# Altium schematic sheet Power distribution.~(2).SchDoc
size A3; SheetNumber: 4; SheetTotal: 4
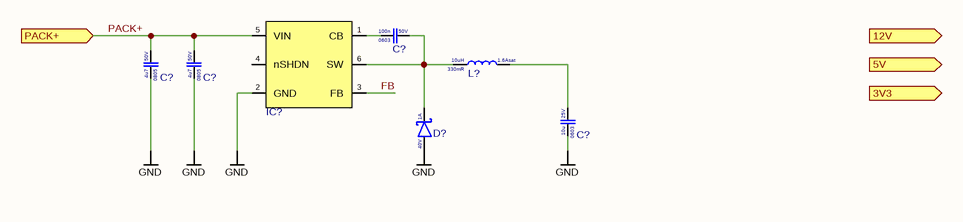
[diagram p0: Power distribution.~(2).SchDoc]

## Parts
(Parts that share a designator on the sheet are numbered #1, #2 ... from top to bottom, then left to right.)
C?#1  Voltage Rating: 50V  Case Code (Imperial): 0603  Capacitance: 100n  [CAP 0603]  (hidden comment: CC0603KRX7R9BB104)
C?#2  Voltage Rating: 50V  Case Code (Imperial): 0805  Capacitance: 4u7  [Cap_0805]  (hidden comment: CL21A475KBQNNNE)
C?#3  Voltage Rating: 50V  Case Code (Imperial): 0805  Capacitance: 4u7  [Cap_0805]  (hidden comment: CL21A475KBQNNNE)
C?#4  Voltage Rating: 25V  Case Code (Imperial): 0603  Capacitance: 10u  [CAP 0603]  (hidden comment: CL10A106MA8NRNC)
D?  Forward Current: 1A  Reverse Voltage: 40V  [SOD-323]  (hidden comment: 1N5819WS)
IC?  LV2842XLVDDCR  [SOT-23-6]  (value not drawn)
L?  Resistance: 330mR  Saturation current: 1.6Asat  Inductance: 10uH  [IND 1008]  (hidden comment: FTC252012S100MBCA)

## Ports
3V3 (out, see Arhitecture[5C]), 5V (out, see Arhitecture[5C]), 12V (out, see Arhitecture[5C], Charger[1A]), PACK+ (in, see Arhitecture[6C], Battery level indicator[3B], Charger[8A])

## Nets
GND: C?#2.1 C?#3.1 C?#4.1 D?.A IC?.2(GND)
FB: IC?.3(FB)
PACK+: C?#2.2 C?#3.2 IC?.5(VIN) ; port PACK+
NetC?#1_1: C?#1.1 IC?.1(CB)
NetC?#1_2: C?#1.2 D?.K IC?.6(SW) L?.1
NetC?#4_2: C?#4.2 L?.2

Not connected (* = marked no-connect by the designer): IC? 4(nSHDN)

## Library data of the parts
C?#1 = CC0603KRX7R9BB104: Cap 100nF 50V 0603 X7R; Manufacturer: Yageo
C?#2 C?#3 = CL21A475KBQNNNE: Cap 4.7uF 50V 0805 X5R; Manufacturer: Samsung
C?#4 = CL10A106MA8NRNC: Cap 10uF 25V 0603 X5R; Manufacturer: Samsung
D? = 1N5819WS: Schottky 40V 1A 600mVf SOD-323; Manufacturer: Guangdong Hottech
IC? = LV2842XLVDDCR: Step-down converter 4~40Vin 600mAout Adjustible SOT23-6; Manufacturer: Texas Instruments
L? = FTC252012S100MBCA: Inductor 10uH 1.6Asat 330mR; Manufacturer: cjiang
